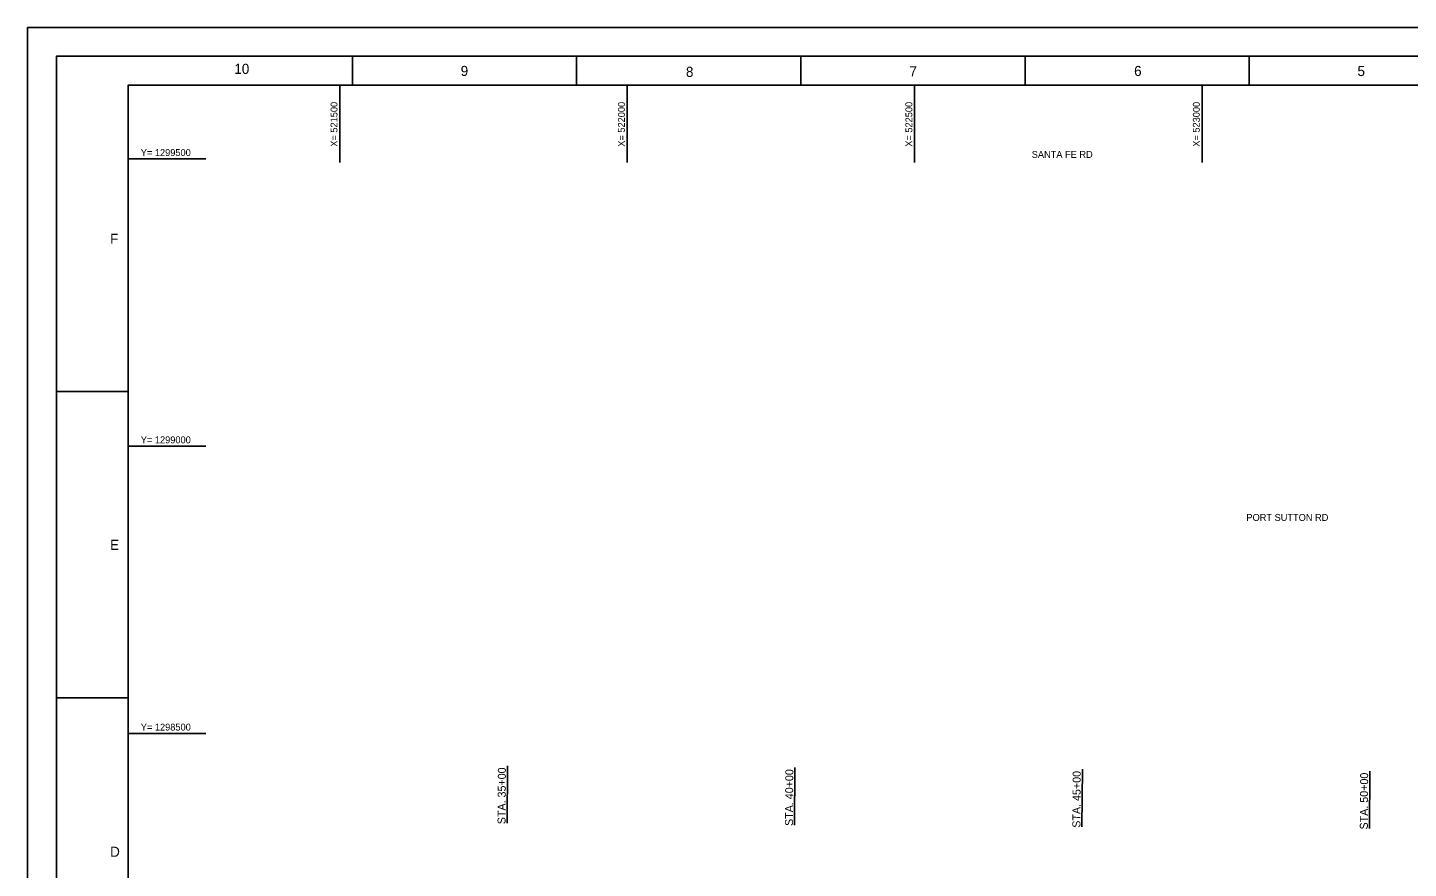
# Model space of a CAD drawing. Extents: x 520957 to 525357, y 1296329 to 1299729.
# Drawn here: x 520957 to 523359, y 1298265 to 1299729 of the extents above; entities that cross this region are included whole.
import ezdxf

# ---------------------------------------------------------------- set-up
doc = ezdxf.new("R2010")
doc.units = 0
for name, color, linetype in [('G-ANNO-NPLT', 7, 'Continuous'), ('G-ANNO-TTLB', 7, 'Continuous'), ('V-ALGN-TEXT', 7, 'Continuous'), ('V-ROAD-IDEN', 7, 'Continuous'), ('V-TOPO-COOR-STAT', 7, 'Continuous')]:
    doc.layers.add(name, color=color, linetype=linetype)

msp = doc.modelspace()

# ---------------------------------------------------------------- linework, layer by layer
at = {"layer": 'G-ANNO-NPLT'}
msp.add_lwpolyline([(520957.1, 1299728.6), (525357, 1299728.6), (525357, 1296328.6), (520957.1, 1296328.6)], close=True, dxfattribs=at)
msp.add_lwpolyline([(520957.1, 1299678.6), (520957.1, 1299728.6), (521007.1, 1299728.6)], dxfattribs=at)
at = {"layer": 'G-ANNO-TTLB'}
for p, q in [((521522.1, 1299678.6), (521522.1, 1299628.6)), ((521912.1, 1299678.6), (521912.1, 1299628.6)), ((521912.1, 1299678.6), (521912.1, 1299628.6)), ((522302.1, 1299678.6), (522302.1, 1299628.6)), ((522692.1, 1299678.6), (522692.1, 1299628.6)), ((523082, 1299678.6), (523082, 1299628.6)), ((521007.1, 1299095.1), (521132.1, 1299095.1)), ((521007.1, 1298561.8), (521132.1, 1298561.8))]:
    msp.add_line(p, q, dxfattribs=at)
for points in [[(521007.1, 1296378.6), (525307, 1296378.6), (525307, 1299678.6), (521007.1, 1299678.6)], [(525257, 1299628.6), (521132.1, 1299628.6), (521132.1, 1296428.6), (525257, 1296428.6)]]:
    msp.add_lwpolyline(points, close=True, dxfattribs=at)
at = {"layer": 'V-ALGN-TEXT'}
for p, q in [((521791.2, 1298343.6), (521791.8, 1298443.6)), ((522291.2, 1298340.5), (522291.8, 1298440.5)), ((522791.1, 1298337.5), (522791.8, 1298437.5)), ((523291.1, 1298334.4), (523291.7, 1298434.4))]:
    msp.add_line(p, q, dxfattribs=at)
at = {"layer": 'V-TOPO-COOR-STAT'}
for p, q in [((521500, 1299493.6), (521500, 1299628.6)), ((522000, 1299493.6), (522000, 1299628.6)), ((522500, 1299493.6), (522500, 1299628.6)), ((523000, 1299493.6), (523000, 1299628.6)), ((521267.1, 1299500), (521132.1, 1299500)), ((521267.1, 1299000), (521132.1, 1299000)), ((521267.1, 1298500), (521132.1, 1298500))]:
    msp.add_line(p, q, dxfattribs=at)

# ---------------------------------------------------------------- texts
at = {"layer": 'G-ANNO-TTLB'}
for s, p in [('10', (521316.6, 1299648)), ('9', (521710.4, 1299644.5)), ('8', (522102.2, 1299642.8)), ('7', (522490.9, 1299643.6)), ('6', (522881.8, 1299644.3)), ('5', (523270.3, 1299644.2)), ('F', (521100.6, 1299352.2)), ('E', (521100.5, 1298819.5)), ('D', (521100.6, 1298285.3))]:
    msp.add_text(s, height=17.5, dxfattribs=at).set_placement(p)
at = {"layer": 'V-ALGN-TEXT'}
for s, p in [('STA. 35+00', (521788.4, 1298341.9)), ('STA. 40+00', (522288.4, 1298338.9)), ('STA. 45+00', (522788.3, 1298335.8)), ('STA. 50+00', (523288.3, 1298332.8))]:
    msp.add_text(s, height=13.92, rotation=89.6504, dxfattribs=at).set_placement(p)
at = {"layer": 'V-ROAD-IDEN'}
for s, p in [('SANTA FE RD', (522703.7, 1299501.8)), ('PORT SUTTON RD', (523077.1, 1298869.9))]:
    msp.add_text(s, height=12, dxfattribs=at).set_placement(p)
at = {"layer": 'V-TOPO-COOR-STAT'}
for s, p in [('X= 521500', (521496, 1299521.2)), ('X= 522000', (521996, 1299521.2)), ('X= 522500', (522496, 1299521.2)), ('X= 523000', (522996, 1299521.2))]:
    msp.add_text(s, height=12, rotation=90, dxfattribs=at).set_placement(p)
for s, p in [('Y= 1299500', (521153.9, 1299505)), ('Y= 1299000', (521153.9, 1299005)), ('Y= 1298500', (521153.9, 1298505))]:
    msp.add_text(s, height=12, dxfattribs=at).set_placement(p)

doc.saveas('drawing.dxf')
